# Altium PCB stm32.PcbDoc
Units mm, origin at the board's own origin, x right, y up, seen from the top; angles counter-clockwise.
Board outline 152.4 x 101.6 mm, 2 copper layers (Top Layer, Bottom Layer); 20 components, 38 nets, 143 pads, 4 vias.
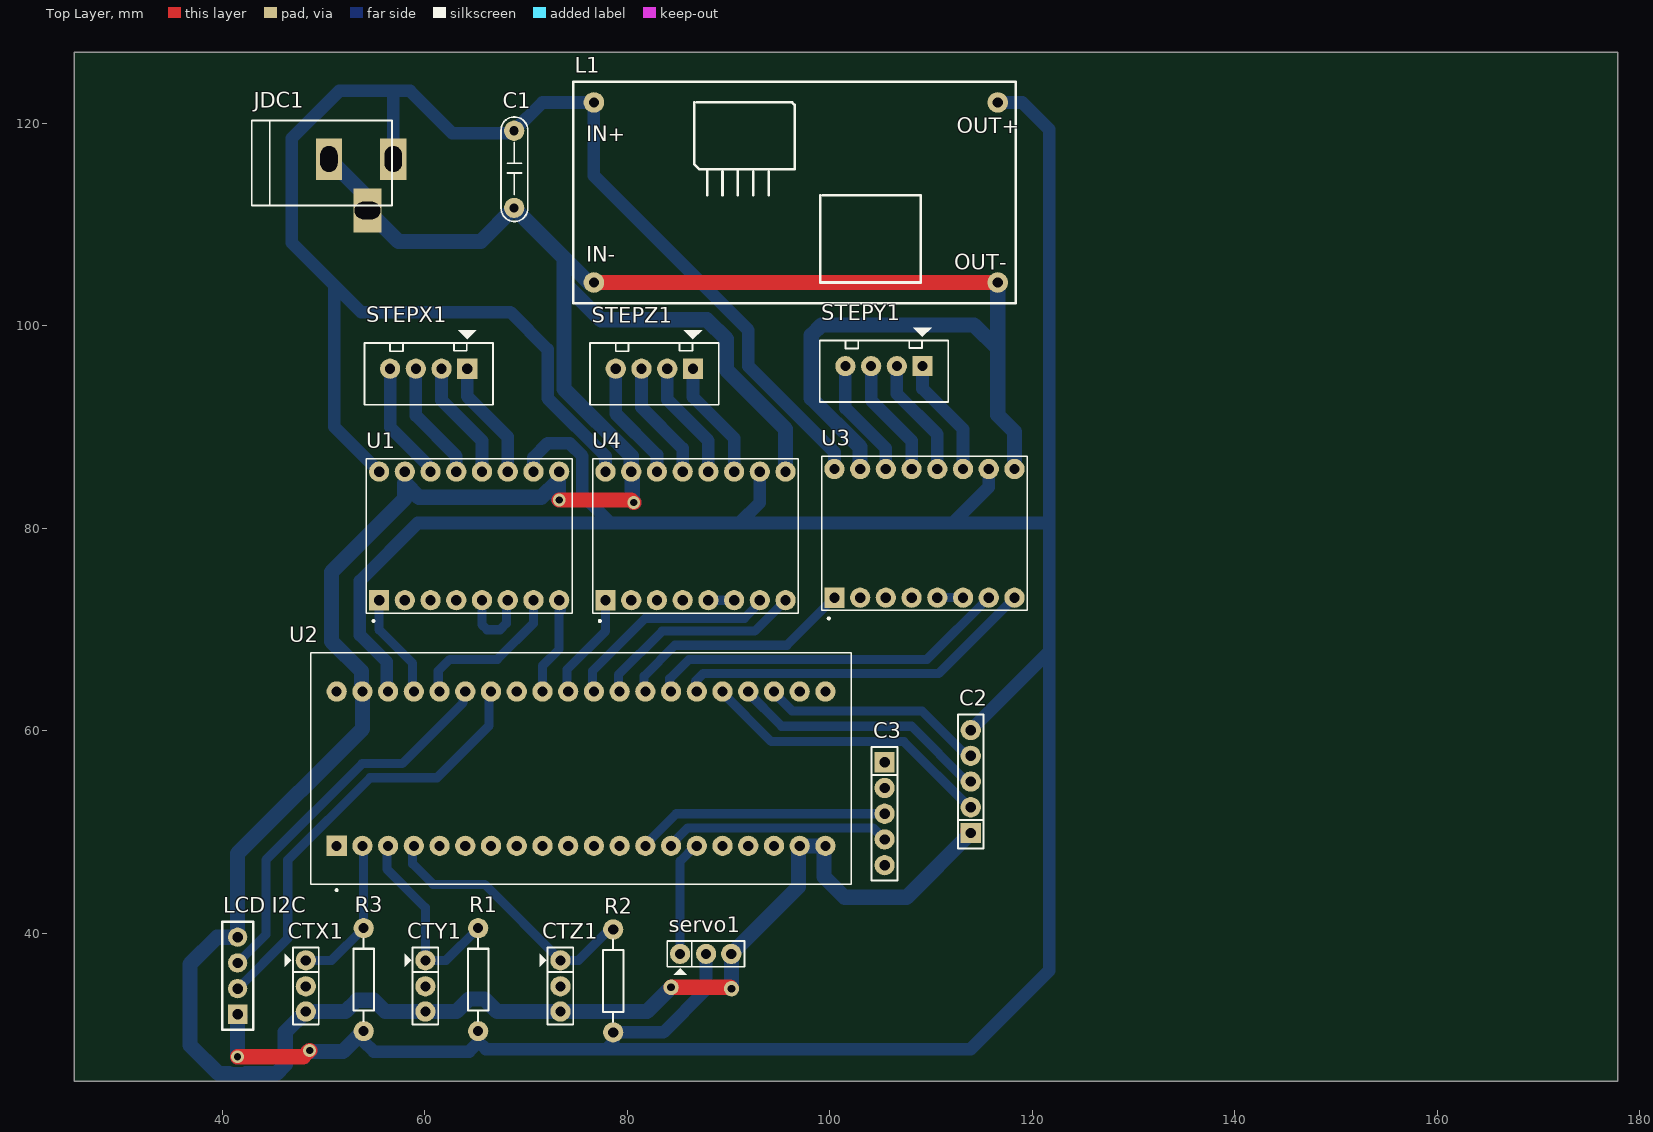
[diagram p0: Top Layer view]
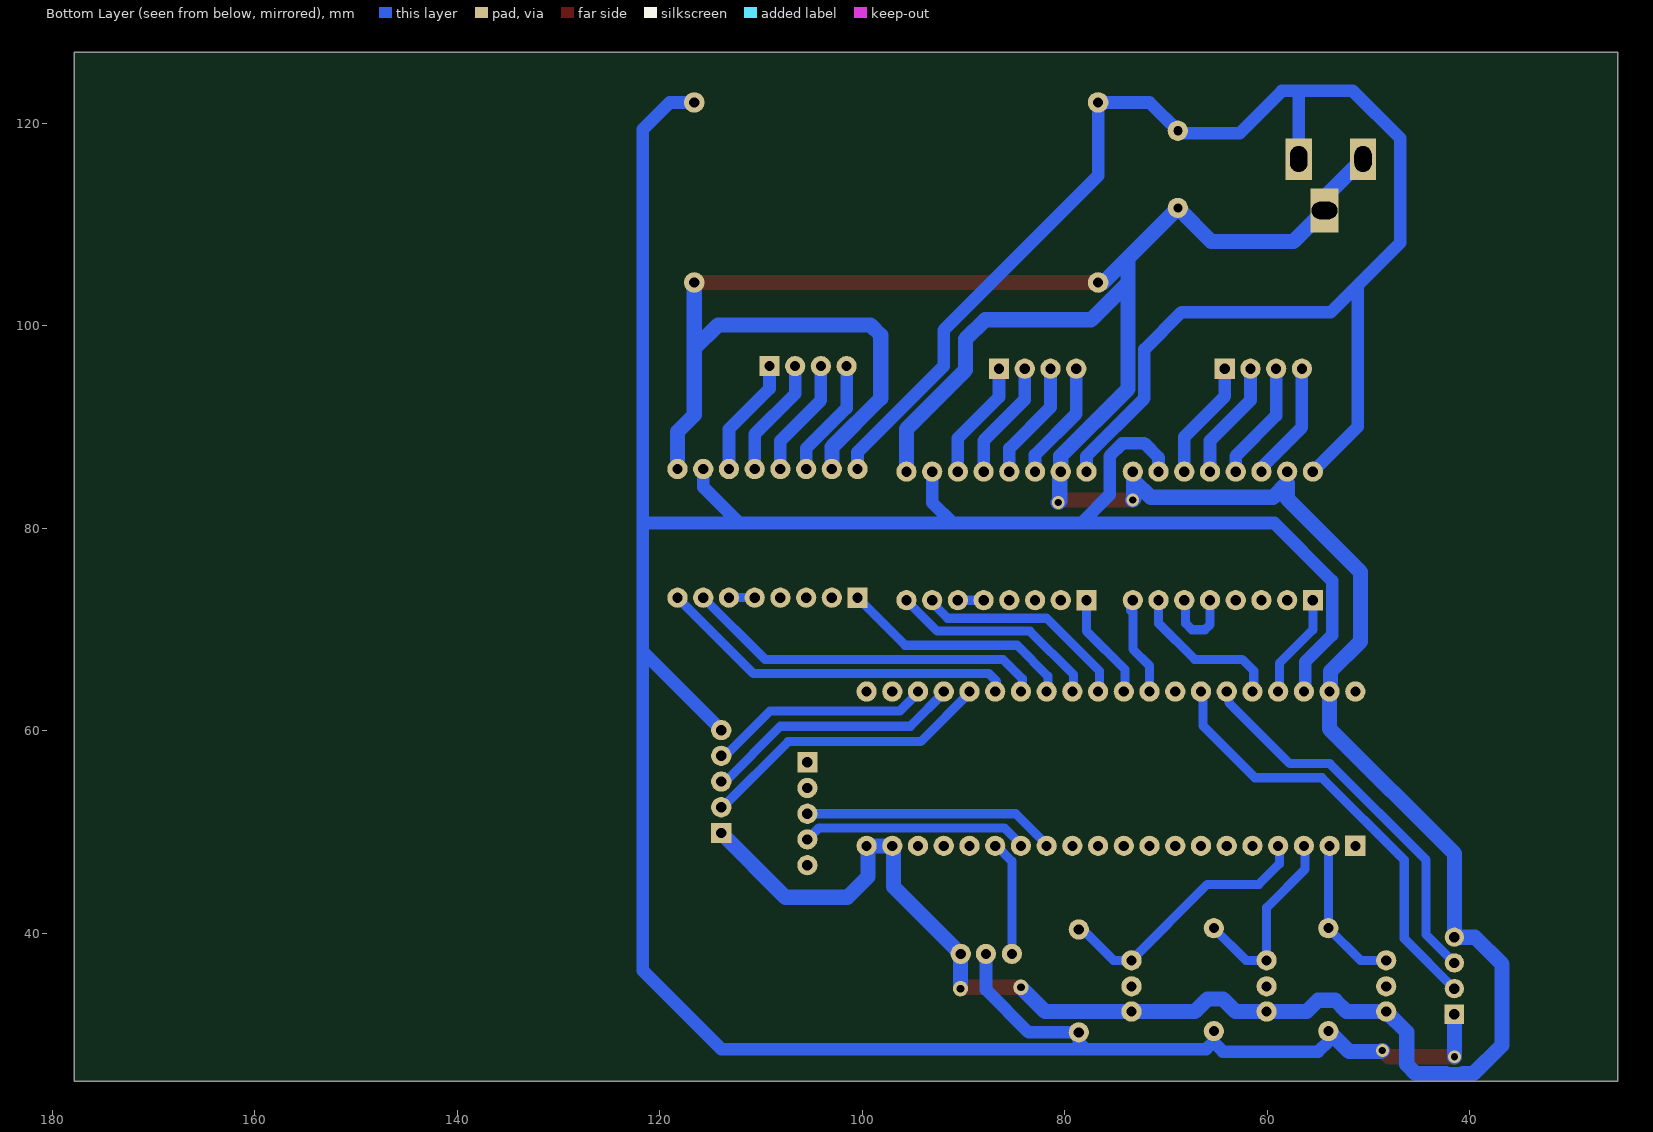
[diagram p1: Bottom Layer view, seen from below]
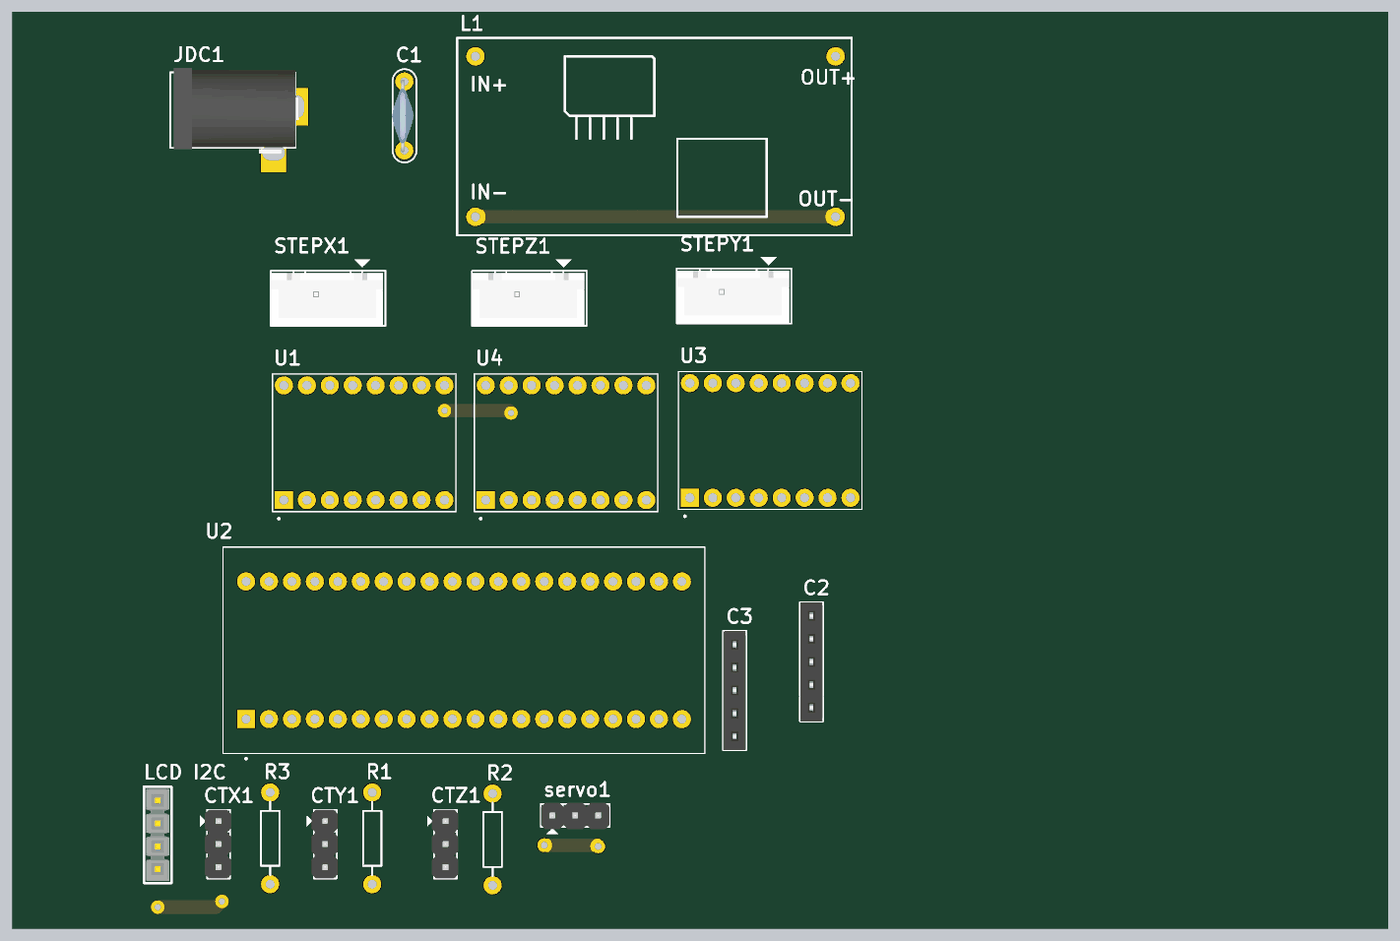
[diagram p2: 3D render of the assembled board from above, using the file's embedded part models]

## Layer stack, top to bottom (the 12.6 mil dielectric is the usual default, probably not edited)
Top Solder: solder mask 0.0102, Solder Resist, Dk 3.5
Top Layer: signal copper 0.0356
Dielectric 1: dielectric 0.32, FR-4, Dk 4.8
Bottom Layer: signal copper 0.0356
Bottom Solder: solder mask 0.0102, Solder Resist, Dk 3.5

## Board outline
25.4,25.4 177.8,25.4 177.8,127 25.4,127

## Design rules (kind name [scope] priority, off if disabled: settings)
Clearance [All] p1: gap=0.254 ignorepadtopadclearanceinfootprint=FALSE except(0: Arc-Hole Track-Hole SMDPad-Hole THPad-Hole Via-Hole Fill-Hole Poly-Hole Region-Hole Text-Hole)
PolygonConnect [All] p1: connectstyle=Relief reliefconductorwidth=0.254 reliefentries=4 polygonreliefangle="90 Angle" airgapwidth=0.254
RoutingVias [All] p1: holewidth=0.711 width=1.27 viastyle="Through Hole" minholewidth=0.711 minwidth=1.27 maxholewidth=0.711 maxwidth=1.27
SolderMaskExpansion [All] p1: expansion=0.102 istentingtop=FALSE
Width [All] p1: maxlimit=1.5 minlimit=0.9 preferedwidth=1.25 minimp=50.000000 maximp=50.000000 favimp=50.000000
30 further rules are at their usual default settings.

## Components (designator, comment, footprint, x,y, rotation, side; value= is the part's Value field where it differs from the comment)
C1 "104" CN3 68.834,115.443 r90 top value=0,047uF
C2 "JP5" JP5-C1T 113.919,49.911 r90 top
C3 "JP5" JP5-C1T 105.41,56.896 r270 top
CTX1 "Jumper 3" JP3 48.26,34.798 r270 top value=J3
CTY1 "Jumper 3" JP3 60.071,34.798 r270 top value=J3
CTZ1 "Jumper 3" JP3 73.406,34.798 r270 top value=J3
JDC1 "Jac DC" DC-IN 56.896,116.459 r0 top
L1 "BUCK_LM2596" BUCK_LM2596 96.266,113.919 r0 top
"LCD I2C" "Header 4" "Header 4" 41.529,32.004 r90 top
R1 "Res2" AXIAL-0.4 65.278,35.433 r270 top value=10K
R2 "Res2" AXIAL-0.4 78.613,35.306 r270 top value=10K
R3 "Res2" AXIAL-0.4 53.975,35.433 r90 top value=10K
servo1 "Jumper 3" JP3 87.757,37.973 r0 top value=J3
STEPX1 "JP4" CON4 64.203,95.758 r180 top value="Connector 4"
STEPY1 "JP4" CON4 109.161,96.012 r180 top value="Connector 4"
STEPZ1 "JP4" CON4 86.487,95.758 r180 top value="Connector 4"
U1 "A4988" MODULE_A4988_STEPPER_MOTOR_DRIVER_CARRIER_BLACK 64.389,79.248 r90 top
U2 "ZC323000" MODULE_ZC323000 75.438,56.261 r90 top
U3 "A4988" MODULE_A4988_STEPPER_MOTOR_DRIVER_CARRIER_BLACK 109.347,79.502 r90 top
U4 "A4988" MODULE_A4988_STEPPER_MOTOR_DRIVER_CARRIER_BLACK 86.741,79.248 r90 top

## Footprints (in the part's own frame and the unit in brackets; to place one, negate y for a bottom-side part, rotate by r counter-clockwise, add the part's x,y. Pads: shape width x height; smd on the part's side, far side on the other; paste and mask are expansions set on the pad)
AXIAL-0.4 [mm] "Axial Device, Thru-Hole; 2 Leads; 0.4 in Pin Spacing"
  round 2 hole 1: 1(-5.08,0) 2(5.08,0)
  silkscreen extent -4.06,-1.02 4.06,1.02
BUCK_LM2596 [mil]
  round 80 hole 40: 1(-770,320) 2(-770,-380) 3(800,-380) 4(800,320)
  silkscreen extent -850,-460 870,400
CN3 [mm] "Cap np W 0.3"
  round 2 hole 0.9: 1(-3.81,0) 2(3.81,0)
  silkscreen extent -5.15,-1.35 5.18,1.3, body extent -4,-1.02 4,1.38, height 10.65
CON4 [mm] "CON4"
  rect 2x2 hole 1: 1(0,0)
  round 2 hole 1: 2(2.54,0) 3(5.08,0) 4(7.62,0)
  silkscreen extent -2.54,-3.8 10.16,3.56, body extent -2.29,-2.29 10.11,3.46, height 7
DC-IN [mm] "Jac DC input"
  rect 2.6x4.1 hole 1.7 slot 2.54 at 90 deg: 1(0,0) 2(-6.35,0)
  rect 2.8x4.3 hole 1.7 slot 2.54 at 0 deg: 3(-2.54,-5.08)
  silkscreen extent -13.97,-4.57 -0.13,3.81, body extent -13.6,-5.21 0.23,4.3, height 11.02
"Header 4" [mil] "Connector; Header; 4 Position; Solder Pad 35mil"
  rect 75x75 hole 40: 1(0,0)
  round 75 hole 40: 2(100,0) 3(200,0) 4(300,0)
  silkscreen extent -60,-60 360,60, body extent -50,-50 350,50, height 330
JP3 [mm] "Jumper 3"
  round 2 hole 1: 1(-2.54,0) 2(0.025,0) 3(2.515,0)
  silkscreen extent -3.81,-2.06 3.81,1.27, body extent -3.81,-1.52 3.81,1.4, height 9.02
JP5-C1T [mm] "5 row, straight, gold plating"
  rect 2x2 hole 1.02: 1(0,0)
  round 2 hole 1.02: 2(2.54,0) 3(5.08,0) 4(7.62,0) 5(10.16,0)
  silkscreen extent -1.52,-1.27 11.68,1.27, body extent -1.52,-1.25 11.68,1.25, height 8.51
MODULE_A4988_STEPPER_MOTOR_DRIVER_CARRIER_BLACK [mm]
  rect 2x2 hole 1.02: 1(-6.35,8.89)
  round 2 hole 1.02: 2(-6.35,6.35) 3(-6.35,3.81) 4(-6.35,1.27) 5(-6.35,-1.27) 6(-6.35,-3.81) 7(-6.35,-6.35) 8(-6.35,-8.89) 9(6.35,-8.89) 10(6.35,-6.35) 11(6.35,-3.81) 12(6.35,-1.27) 13(6.35,1.27) 14(6.35,3.81) 15(6.35,6.35) 16(6.35,8.89)
  silkscreen extent -8.5,-10.16 7.62,10.16
MODULE_ZC323000 [mm]
  rect 2x2 hole 1: 1(-7.62,24.13)
  round 2 hole 1: 2(-7.62,21.59) 3(-7.62,19.05) 4(-7.62,16.51) 5(-7.62,13.97) 6(-7.62,11.43) 7(-7.62,8.89) 8(-7.62,6.35) 9(-7.62,3.81) 10(-7.62,1.27) 11(-7.62,-1.27) 12(-7.62,-3.81) 13(-7.62,-6.35) 14(-7.62,-8.89) 15(-7.62,-11.43) 16(-7.62,-13.97) 17(-7.62,-16.51) 18(-7.62,-19.05) 19(-7.62,-21.59) 20(-7.62,-24.13) 21(7.62,-24.13) 22(7.62,-21.59) 23(7.62,-19.05) 24(7.62,-16.51) 25(7.62,-13.97) 26(7.62,-11.43) 27(7.62,-8.89) 28(7.62,-6.35) 29(7.62,-3.81) 30(7.62,-1.27) 31(7.62,1.27) 32(7.62,3.81) 33(7.62,6.35) 34(7.62,8.89) 35(7.62,11.43) 36(7.62,13.97) 37(7.62,16.51) 38(7.62,19.05) 39(7.62,21.59) 40(7.62,24.13)
  silkscreen extent -12.1,-26.67 11.43,26.67

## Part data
C1: library part CN3, "Cap np W0.3"
C2 C3: "WR-PHD 2.54 mm Angled Socket Header", Manufacturer="W¨¹rth Elektronik eiSos GmbH", partNo=613005143121
CTX1 CTY1 CTZ1 servo1: library part JP3
JDC1: library part DCIN, "Jac DC input"
"LCD I2C": "Header, 4-Pin"
R1 R2 R3: "Resistor"
STEPX1 STEPY1 STEPZ1: library part Con4, "Connector 4"
U1 U3 U4: library part A4988_STEPPER_MOTOR_DRIVER_CARRIER_BLACK, "Stepper motor controler; IC: A4988; 1.2A; Uin mot: 8Ã·35V", Package=None
U2: "STM32F103C8T6 ARM STM32 Minimum System Development Board Module For Arduino", Package=None

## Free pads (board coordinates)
  round 1.524 hole 0.762: 3(90.297,34.544) pv(84.328,34.671)

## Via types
v1: diameter 1.27, hole 0.711, Top Layer to Bottom Layer, 4 vias

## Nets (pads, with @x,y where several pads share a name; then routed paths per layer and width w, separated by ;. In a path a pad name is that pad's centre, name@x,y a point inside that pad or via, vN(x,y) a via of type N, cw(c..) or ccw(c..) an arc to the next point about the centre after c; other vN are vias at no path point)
1: STEPX1.2 U1.12 | length 11.8
  Bottom Layer w1.25: STEPX1.2 61.663,92.642 65.659,88.646 U1.12
2: STEPX1.1 U1.11 | length 11.8
  Bottom Layer w1.25: STEPX1.1 64.203,93.023 68.199,89.027 U1.11
3: STEPX1.3 U1.13 | length 11.8
  Bottom Layer w1.25: STEPX1.3 59.123,91.118 63.119,87.122 U1.13
4: STEPX1.4 U1.14 | length 11.8
  Bottom Layer w1.25: STEPX1.4 56.583,89.975 60.579,85.979 U1.14
5: STEPY1.2 U3.12 | length 11.8
  Bottom Layer w1.25: STEPY1.2 106.621,93.277 110.617,89.281 U3.12
6: STEPY1.1 U3.11 | length 11.8
  Bottom Layer w1.25: STEPY1.1 109.161,93.785 113.157,89.789 U3.11
7: STEPY1.3 U3.13 | length 11.8
  Bottom Layer w1.25: STEPY1.3 104.081,92.642 108.077,88.646 U3.13
8: STEPY1.4 U3.14 | length 11.8
  Bottom Layer w1.25: STEPY1.4 101.541,91.88 105.537,87.884 U3.14
9: STEPZ1.2 U4.12 | length 11.8
  Bottom Layer w1.25: STEPZ1.2 83.947,92.71 88.011,88.646 U4.12
10: STEPZ1.1 U4.11 | length 11.8
  Bottom Layer w1.25: STEPZ1.1 86.487,92.964 90.551,88.9 U4.11
11: STEPZ1.3 U4.13 | length 11.8
  Bottom Layer w1.25: STEPZ1.3 81.407,91.948 85.471,87.884 U4.13
12: STEPZ1.4 U4.14 | length 11.8
  Bottom Layer w1.25: STEPZ1.4 78.867,91.313 82.931,87.249 U4.14
+5: "LCD I2C.1" C2.5 L1.4 R1.2 R2.2 R3.1 servo1.2 U1.10 U2.38 U3.10 U4.10 | length 318.1
  Top Layer w1.5: v1(41.529,27.813) 48.006,27.813 v1(48.641,28.448)
  Bottom Layer w1.25: 53.975,29.337 54.991,28.321 64.389,28.321 65.278,29.21 ; U2.38@56.261,63.881 56.261,66.802 53.594,69.469 53.594,74.803 59.309,80.518 78.359,80.518 ; R1.2 65.278,29.337 66.04,28.575 77.978,28.575 ; U1.10 70.739,86.995 72.136,88.392 74.295,88.392 75.565,87.122 75.565,83.312 78.359,80.518 ; servo1.2 87.782,34.442 83.566,30.226 R2.2 78.613,29.21 77.978,28.575 ; U4.10 93.091,82.55 91.059,80.518 ; C2.5 121.666,67.818 ; U3.10 115.697,84.074 112.141,80.518 ; L1.4 118.999,122.047 121.666,119.38 121.666,80.645 ; 77.978,28.575 113.919,28.575 121.666,36.322 121.666,67.818 ; 78.359,80.518 91.059,80.518 ; 91.059,80.518 112.141,80.518 ; 112.141,80.518 121.539,80.518 121.666,80.645 ; 121.666,67.818 121.666,80.645
  Bottom Layer w1.5: v1(41.529,27.813) 41.529,32.004 41.731,31.802 ; v1(48.641,28.448) 48.768,28.321 51.943,28.321 R3.1 ; C2.5 C2.5@114.054,60.071
+12: C1.2 JDC1.1 L1.1 U1.16 U3.16 U4.16 | length 162.3
  Bottom Layer w1.25: U1.16 51.054,90.043 51.054,104.013 ; JDC1.1 56.896,122.809 56.515,123.19 ; U4.16 77.851,87.122 72.136,92.837 72.136,97.663 68.453,101.346 53.721,101.346 51.054,104.013 ; U3.16 100.457,87.503 91.948,96.012 91.948,99.568 76.708,114.808 L1.1 71.628,122.047 C1.2 68.58,118.999 62.738,118.999 58.547,123.19 56.515,123.19 ; 51.054,104.013 46.863,108.204 46.863,118.491 51.562,123.19 56.515,123.19
ctx: CTX1.1 R3.2 U2.2 | length 15.3
  Bottom Layer w0.9: CTX1.1 50.8,37.338 R3.2 53.975,48.387 U2.2@53.721,48.641
cty: CTY1.1 R1.1 U2.3 | length 19.4
  Bottom Layer w0.9: U2.3@56.261,48.641 56.261,46.355 60.071,42.545 CTY1.1 62.103,37.338 R1.1
ctz: CTZ1.1 R2.1 U2.4 | length 26.8
  Bottom Layer w0.9: U2.4@58.801,48.641 58.801,46.863 60.833,44.831 65.913,44.831 CTZ1.1 75.184,37.338 78.232,40.386 R2.1
dirx: U1.8 U2.32 | length 9.8
  Bottom Layer w0.9: U2.32 71.628,66.421 73.279,68.072 U1.8@73.279,71.91 ; U1.8 73.489,72.688 73.489,71.91
diry: U2.26 U3.8 | length 35.9
  Bottom Layer w0.9: U2.26@86.741,63.881 86.741,64.897 87.503,65.659 110.744,65.659 U3.8
dirz: U2.29 U4.8 | length 21.2
  Bottom Layer w0.9: U2.29@79.121,63.881 79.121,65.532 83.439,69.85 92.583,69.85 U4.8
enx: U1.1 U2.37 | length 10.4
  Bottom Layer w0.9: U1.1 55.499,69.977 58.801,66.675 U2.37@58.801,63.881
eny: U2.28 U3.1 | length 23.5
  Bottom Layer w0.9: U2.28@81.661,63.881 81.661,65.405 84.709,68.453 95.758,68.453 U3.1
enz: U2.31 U4.1 | length 10.6
  Bottom Layer w0.9: U2.31@74.041,63.881 74.041,66.04 77.851,69.85 U4.1
GND: "LCD I2C.4" C1.1 C2.1 CTX1.3 CTY1.3 CTZ1.3 JDC1.2 JDC1.3 L1.2 L1.3 pad.3 pad.pv servo1.3 U1.9 U1.15 U2.19 U2.20 U2.39 U3.9 U3.15 U4.9 U4.15 | length 387.3
  Top Layer w1.5: v1(73.279,82.804) 80.391,82.804 v1(80.645,82.55) ; L1.2 L1.3 ; U4.15@80.391,85.463 U4.15 ; pad.pv 90.17,34.671 pad.3 ; C2.1@113.669,50.161 C2.1
  Bottom Layer w1.5: JDC1.2 54.356,112.649 JDC1.3 57.404,108.331 65.532,108.331 C1.1 73.765,106.702 ; v1(73.279,82.804) 73.183,82.9 U1.9@73.183,84.74 ; U1.9 73.183,85.502 U1.9@73.183,84.74 ; L1.2 76.2,104.267 73.765,106.702 ; v1(80.645,82.55) 80.487,82.708 80.487,85.502 U4.15 80.391,87.122 73.765,93.748 73.765,104.221 ; pad.pv 81.939,32.282 73.406,32.282 CTZ1.3 67.158,32.283 65.913,33.528 64.389,33.528 63.144,32.283 CTY1.3 56.109,32.283 54.991,33.401 53.289,33.401 52.172,32.283 CTX1.3 46.228,30.251 46.228,27.041 45.349,26.162 42.359,26.162 42.256,26.059 40.802,26.059 40.699,26.162 39.624,26.162 36.83,28.956 36.83,36.957 39.494,39.621 41.526,39.621 41.529,39.624 41.529,47.879 53.848,60.198 U2.39 53.752,63.977 53.752,65.882 50.8,68.834 50.8,75.692 58.039,82.931 58.039,84.455 59.436,83.058 71.501,83.058 U1.9@73.183,84.74 ; pad.3 90.297,37.948 servo1.3 96.901,44.602 96.901,48.641 99.441,48.641 99.441,45.593 101.473,43.561 107.569,43.561 C2.1 ; U4.9 95.631,89.789 89.789,95.631 89.789,98.679 87.884,100.584 77.402,100.584 73.765,104.221 ; U3.15 102.997,88.011 98.171,92.837 98.171,99.06 99.187,100.076 114.236,100.076 116.586,97.727 ; L1.3 116.586,97.727 ; U3.9 118.237,89.535 116.586,91.186 116.586,97.727 ; 73.765,104.221 73.765,106.702
LCD_SCL: "LCD I2C.2" U2.34 | length 43.6
  Bottom Layer w0.9: 41.529,34.544 46.482,39.497 46.482,47.244 54.61,55.372 61.214,55.372 66.348,60.506 66.348,63.681 U2.34
LCD_SDA: "LCD I2C.3" U2.35 | length 38.4
  Bottom Layer w0.9: 41.529,37.084 44.323,39.878 44.323,47.244 53.839,56.76 57.776,56.76 63.798,62.782 63.798,63.671 U2.35
NetU1_5: U1.5 U1.6 | length 7.6
  Bottom Layer w0.9: U1.5 65.659,70.485 66.167,69.977 67.437,69.977 68.072,70.612 68.072,72.771 U1.6
NetU3_5: U3.5 U3.6 | length 2.5
  Bottom Layer w0.9: U3.5 U3.6
NetU4_5: U4.5 U4.6 | length 2.5
  Bottom Layer w0.9: U4.5 U4.6
out: C2.2 U2.25 | length 29.4
  Bottom Layer w0.9: U2.25@89.281,63.881 94.234,58.928 107.315,58.928 113.792,52.451 C2.2
s0: C3.3 U2.13 | length 25.1
  Bottom Layer w0.9: U2.13@81.661,48.641 84.836,51.816 C3.3
s1: C3.4 U2.14 | length 22.4
  Bottom Layer w0.9: U2.14@84.201,48.641 85.979,50.419 104.267,50.419 C3.4
s2: C2.3 U2.24 | length 25.8
  Bottom Layer w0.9: U2.24@91.821,63.881 95.25,60.452 108.077,60.452 113.538,54.991 C2.3
s3: C2.4 U2.23 | length 22.2
  Bottom Layer w0.9: U2.23@94.361,63.881 96.266,61.976 109.093,61.976 113.538,57.531 C2.4
servo: servo1.1 U2.15 | length 11.4
  Bottom Layer w0.9: servo1.1@85.217,37.846 85.217,47.117 U2.15@86.741,48.641
stepx: U1.7 U2.36 | length 15.7
  Bottom Layer w0.9: U2.36@61.341,63.881 61.341,65.913 62.484,67.056 67.183,67.056 70.739,70.612 U1.7
stepy: U2.27 U3.7 | length 36.1
  Bottom Layer w0.9: U2.27@84.201,63.881 84.201,65.151 86.106,67.056 109.601,67.056 U3.7
stepz: U2.30 U4.7 | length 21.6
  Bottom Layer w0.9: U2.30@76.581,63.881 76.581,65.913 81.788,71.12 91.567,71.12 93.091,72.644 U4.7
pads on no net: C3.1 C3.2 C3.5 CTX1.2 CTY1.2 CTZ1.2 U1.2 U1.3 U1.4 U2.1 U2.5 U2.6 U2.7 U2.8 U2.9 U2.10 U2.11 U2.12 U2.16 U2.17 U2.18 U2.21 U2.22 U2.33 U2.40 U3.2 U3.3 U3.4 U4.2 U4.3 U4.4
